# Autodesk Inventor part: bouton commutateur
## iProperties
Author: Administrateur
Created: 2001-04
Part Number: bouton commutateur
Material: Aluminum
Document SubType Name: Modélisation
Designer: Administrateur
Control State: 0
Master: False
Checked Out: False
PropertySet Name: Design Tracking Control
Shininess: 55.0
PropertySet Name: _Private Model Information
Length Units: 11269
Angle Units: 11283
Time Units: 11279
Mass Units: 11290
Length Display Precision: 3
Angle Display Precision: 2
Compacted: False
Density: 0.0
Volumn: 0.0
Area: 0.0
PropertySet Name: Model Information
